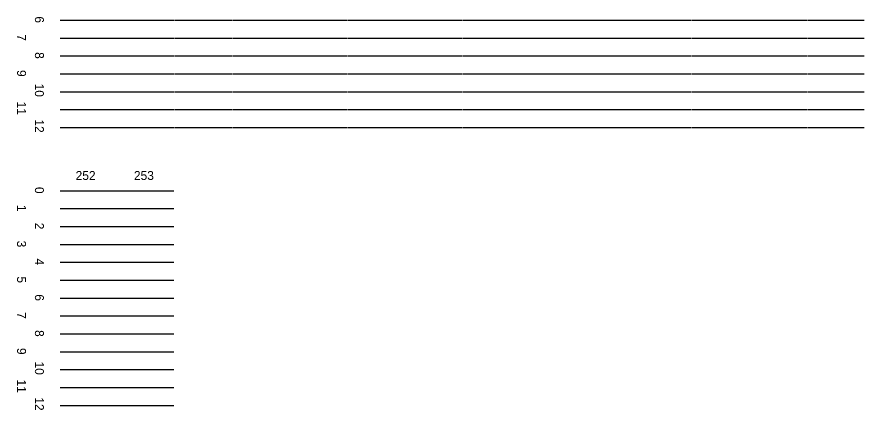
# Model space of a CAD drawing. Extents: x 11193 to 12507, y 10092 to 10555.
# Drawn here: x 11683 to 11888.4, y 10226 to 10321.2 of the extents above; entities that cross this region are included whole.
import ezdxf

# ---------------------------------------------------------------- set-up
doc = ezdxf.new("R2010")
doc.units = 0
doc.layers.add('Level 2', color=7, linetype='Continuous')

msp = doc.modelspace()

# ---------------------------------------------------------------- linework, layer by layer
at = {"layer": 'Level 2'}
for p, q in [((11693.42, 10320.47), (11707.35, 10320.47)), ((11707.47, 10320.47), (11721.03, 10320.47)), ((11721.14, 10320.47), (11735.11, 10320.47)), ((11735.23, 10320.47), (11749.19, 10320.47)), ((11749.31, 10320.47), (11763.08, 10320.47)), ((11763.19, 10320.47), (11776.96, 10320.47)), ((11777.06, 10320.47), (11791.04, 10320.47)), ((11791.14, 10320.47), (11804.92, 10320.47)), ((11805.02, 10320.47), (11819.01, 10320.47)), ((11819.11, 10320.47), (11832.88, 10320.47)), ((11832.98, 10320.47), (11846.56, 10320.47)), ((11846.66, 10320.47), (11860.64, 10320.47)), ((11860.74, 10320.47), (11874.52, 10320.47)), ((11874.63, 10320.47), (11888.36, 10320.47)), ((11693.42, 10316.14), (11707.35, 10316.14)), ((11707.47, 10316.14), (11721.03, 10316.14)), ((11721.14, 10316.14), (11735.11, 10316.14)), ((11735.23, 10316.14), (11749.19, 10316.14)), ((11749.31, 10316.14), (11763.08, 10316.14)), ((11763.19, 10316.14), (11776.96, 10316.14)), ((11777.06, 10316.14), (11791.04, 10316.14)), ((11791.14, 10316.14), (11804.92, 10316.14)), ((11805.02, 10316.14), (11819.01, 10316.14)), ((11819.11, 10316.14), (11832.88, 10316.14)), ((11832.98, 10316.14), (11846.56, 10316.14)), ((11846.66, 10316.14), (11860.64, 10316.14)), ((11860.74, 10316.14), (11874.52, 10316.14)), ((11874.63, 10316.14), (11888.36, 10316.14)), ((11693.42, 10311.8), (11707.35, 10311.8)), ((11707.47, 10311.8), (11721.03, 10311.8)), ((11721.14, 10311.8), (11735.11, 10311.8)), ((11735.23, 10311.8), (11749.19, 10311.8)), ((11749.31, 10311.8), (11763.08, 10311.8)), ((11763.19, 10311.8), (11776.96, 10311.8)), ((11777.06, 10311.8), (11791.04, 10311.8)), ((11791.14, 10311.8), (11804.92, 10311.8)), ((11805.02, 10311.8), (11819.01, 10311.8)), ((11819.11, 10311.8), (11832.88, 10311.8)), ((11832.98, 10311.8), (11846.56, 10311.8)), ((11846.66, 10311.8), (11860.64, 10311.8)), ((11860.74, 10311.8), (11874.52, 10311.8)), ((11874.63, 10311.8), (11888.36, 10311.8)), ((11693.42, 10307.47), (11707.35, 10307.47)), ((11707.47, 10307.47), (11721.03, 10307.47)), ((11721.14, 10307.47), (11735.11, 10307.47)), ((11735.23, 10307.47), (11749.19, 10307.47)), ((11749.31, 10307.47), (11763.08, 10307.47)), ((11763.19, 10307.47), (11776.96, 10307.47)), ((11777.06, 10307.47), (11791.04, 10307.47)), ((11791.14, 10307.47), (11804.92, 10307.47)), ((11805.02, 10307.47), (11819.01, 10307.47)), ((11819.11, 10307.47), (11832.88, 10307.47)), ((11832.98, 10307.47), (11846.56, 10307.47)), ((11846.66, 10307.47), (11860.64, 10307.47)), ((11860.74, 10307.47), (11874.52, 10307.47)), ((11874.63, 10307.47), (11888.36, 10307.47)), ((11693.42, 10303.14), (11707.35, 10303.14)), ((11707.47, 10303.14), (11721.03, 10303.14)), ((11721.14, 10303.14), (11735.11, 10303.14)), ((11735.23, 10303.14), (11749.19, 10303.14)), ((11749.31, 10303.14), (11763.08, 10303.14)), ((11763.19, 10303.14), (11776.96, 10303.14)), ((11777.06, 10303.14), (11791.04, 10303.14)), ((11791.14, 10303.14), (11804.92, 10303.14)), ((11805.02, 10303.14), (11819.01, 10303.14)), ((11819.11, 10303.14), (11832.88, 10303.14)), ((11832.98, 10303.14), (11846.56, 10303.14)), ((11846.66, 10303.14), (11860.64, 10303.14)), ((11860.74, 10303.14), (11874.52, 10303.14)), ((11874.63, 10303.14), (11888.36, 10303.14)), ((11693.42, 10298.81), (11707.35, 10298.81)), ((11707.47, 10298.81), (11721.03, 10298.81)), ((11721.14, 10298.81), (11735.11, 10298.81)), ((11735.23, 10298.81), (11749.19, 10298.81)), ((11749.31, 10298.81), (11763.08, 10298.81)), ((11763.19, 10298.81), (11776.96, 10298.81)), ((11777.06, 10298.81), (11791.04, 10298.81)), ((11791.14, 10298.81), (11804.92, 10298.81)), ((11805.02, 10298.81), (11819.01, 10298.81)), ((11819.11, 10298.81), (11832.88, 10298.81)), ((11832.98, 10298.81), (11846.56, 10298.81)), ((11846.66, 10298.81), (11860.64, 10298.81)), ((11860.74, 10298.81), (11874.52, 10298.81)), ((11874.63, 10298.81), (11888.36, 10298.81)), ((11693.42, 10294.48), (11707.35, 10294.48)), ((11707.47, 10294.48), (11721.03, 10294.48)), ((11721.14, 10294.48), (11735.11, 10294.48)), ((11735.23, 10294.48), (11749.19, 10294.48)), ((11749.31, 10294.48), (11763.08, 10294.48)), ((11763.19, 10294.48), (11776.96, 10294.48)), ((11777.06, 10294.48), (11791.04, 10294.48)), ((11791.14, 10294.48), (11804.92, 10294.48)), ((11805.02, 10294.48), (11819.01, 10294.48)), ((11819.11, 10294.48), (11832.88, 10294.48)), ((11832.98, 10294.48), (11846.56, 10294.48)), ((11846.66, 10294.48), (11860.64, 10294.48)), ((11860.74, 10294.48), (11874.52, 10294.48)), ((11874.63, 10294.48), (11888.36, 10294.48)), ((11693.42, 10279.15), (11707.35, 10279.15)), ((11707.47, 10279.15), (11721.03, 10279.15)), ((11693.42, 10274.82), (11707.35, 10274.82)), ((11707.47, 10274.82), (11721.03, 10274.82)), ((11693.42, 10270.49), (11707.35, 10270.49)), ((11707.47, 10270.49), (11721.03, 10270.49)), ((11693.42, 10266.15), (11707.35, 10266.15)), ((11707.47, 10266.15), (11721.03, 10266.15)), ((11693.42, 10261.82), (11707.35, 10261.82)), ((11707.47, 10261.82), (11721.03, 10261.82)), ((11693.42, 10257.49), (11707.35, 10257.49)), ((11707.47, 10257.49), (11721.03, 10257.49)), ((11693.42, 10253.16), (11707.35, 10253.16)), ((11707.47, 10253.16), (11721.03, 10253.16)), ((11693.42, 10248.83), (11707.35, 10248.83)), ((11707.47, 10248.83), (11721.03, 10248.83)), ((11693.42, 10244.49), (11707.35, 10244.49)), ((11707.47, 10244.49), (11721.03, 10244.49)), ((11693.42, 10240.16), (11707.35, 10240.16)), ((11707.47, 10240.16), (11721.03, 10240.16)), ((11693.42, 10235.83), (11707.35, 10235.83)), ((11707.47, 10235.83), (11721.03, 10235.83)), ((11693.42, 10231.5), (11707.35, 10231.5)), ((11707.47, 10231.5), (11721.03, 10231.5)), ((11693.42, 10227.17), (11707.35, 10227.17)), ((11707.47, 10227.17), (11721.03, 10227.17))]:
    msp.add_line(p, q, dxfattribs=at)

# ---------------------------------------------------------------- texts
for s, height, p in [('6', 2.17, (11687.34, 10321.39)), ('7', 2.17, (11683.01, 10317.06)), ('8', 2.17, (11687.34, 10312.72)), ('9', 2.17, (11683.01, 10308.39)), ('10', 2.166, (11687.34, 10305.1)), ('11', 2.166, (11683.01, 10300.76)), ('12', 2.166, (11687.34, 10296.43)), ('0', 2.17, (11687.34, 10280.07)), ('1', 2.17, (11683.01, 10275.74)), ('2', 2.17, (11687.34, 10271.41)), ('3', 2.17, (11683.01, 10267.07)), ('4', 2.17, (11687.34, 10262.74)), ('5', 2.17, (11683.01, 10258.41)), ('6', 2.17, (11687.34, 10254.08)), ('7', 2.17, (11683.01, 10249.75)), ('8', 2.17, (11687.34, 10245.41)), ('9', 2.17, (11683.01, 10241.08)), ('10', 2.166, (11687.34, 10237.79)), ('11', 2.166, (11683.01, 10233.45)), ('12', 2.166, (11687.34, 10229.12))]:
    msp.add_text(s, height=height, rotation=270, dxfattribs=at).set_placement(p)
for s, p in [('252', (11697.21, 10281.76)), ('253', (11711.34, 10281.76))]:
    msp.add_text(s, height=2.17, dxfattribs=at).set_placement(p)

doc.saveas('drawing.dxf')
